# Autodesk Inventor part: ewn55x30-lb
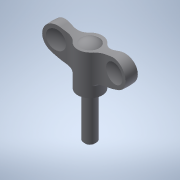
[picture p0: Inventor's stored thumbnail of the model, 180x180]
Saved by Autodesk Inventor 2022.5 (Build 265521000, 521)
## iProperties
Created: 2016-12
Part Number: ewn55x30-lb
Material: 一般
Document SubType Name: Modeling
Designer: imaocorp
Density: 1 g/cm^3
Appearance: 既定
Author: imaocorp
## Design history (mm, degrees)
node "ewn55x30-lb.x_t1"
node "ewn55x30-lb"
node "Base1"
